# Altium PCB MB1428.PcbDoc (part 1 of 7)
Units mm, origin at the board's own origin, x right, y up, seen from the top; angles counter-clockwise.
Board outline 55.88 x 152.4 mm, 4 copper layers (Top Layer, Signal Layer 1, Signal Layer 2, Bottom Layer), stack 1.614 mm thick; 396 components, 227 nets, 1346 pads, 1469 vias.
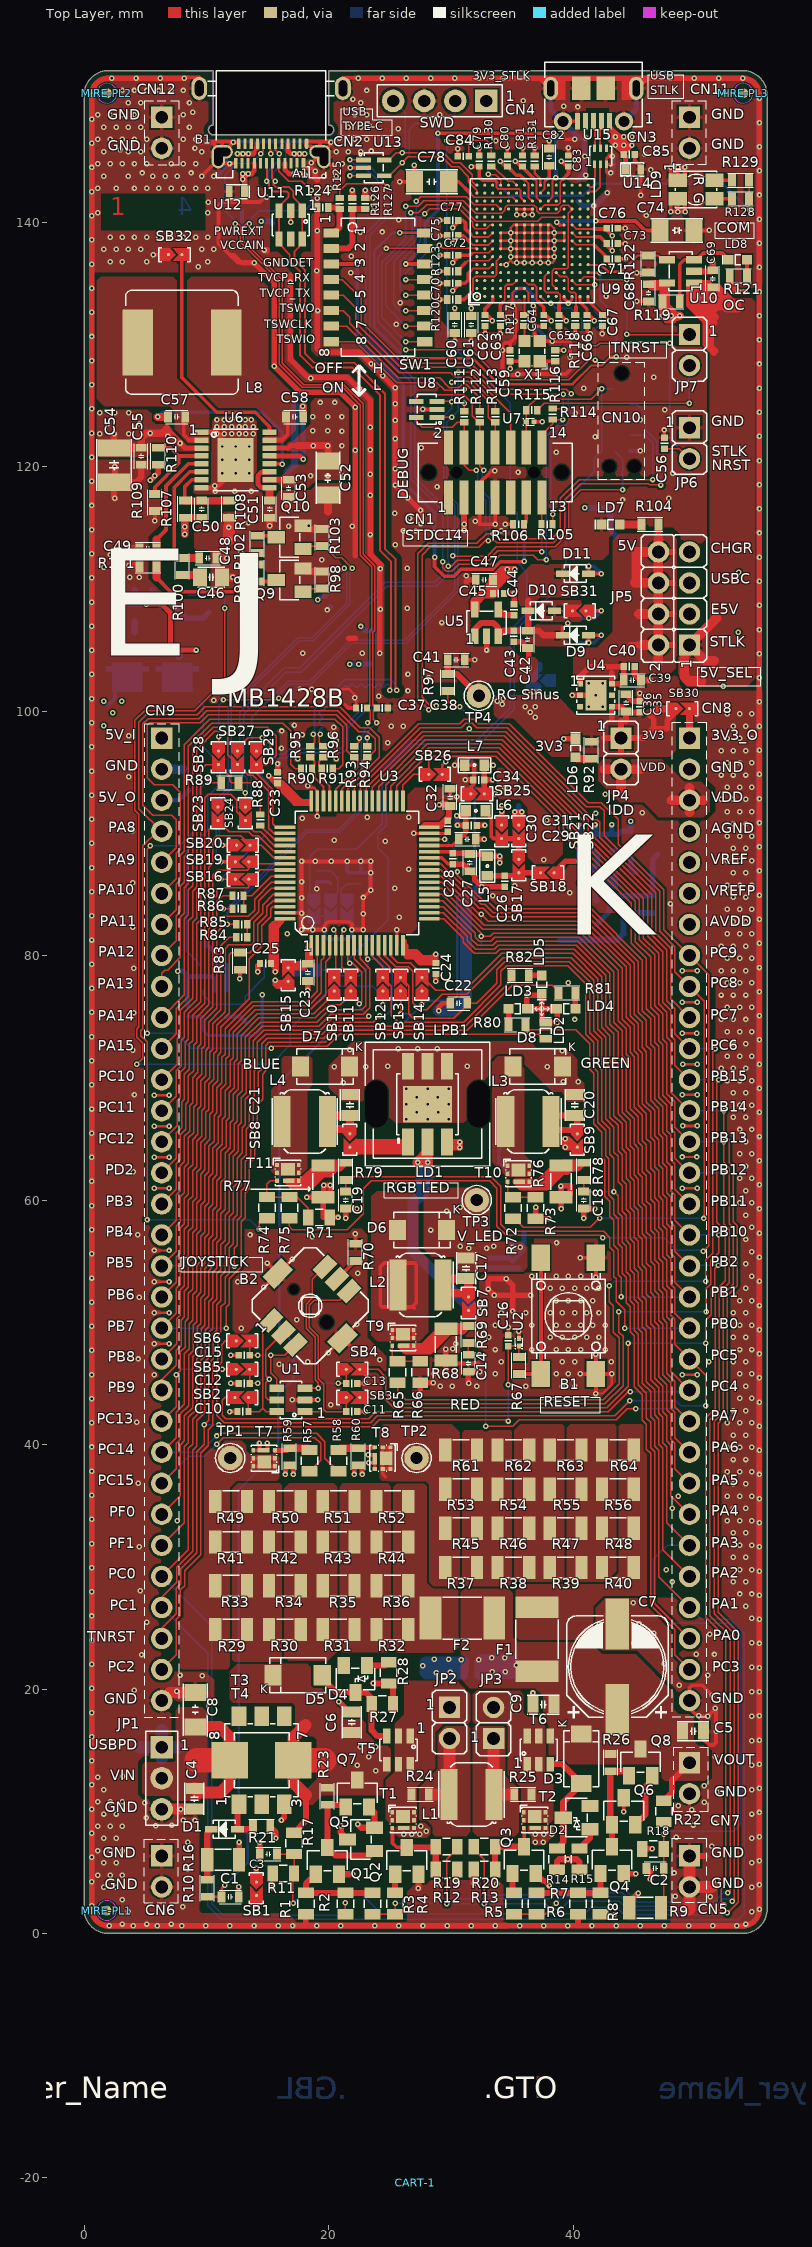
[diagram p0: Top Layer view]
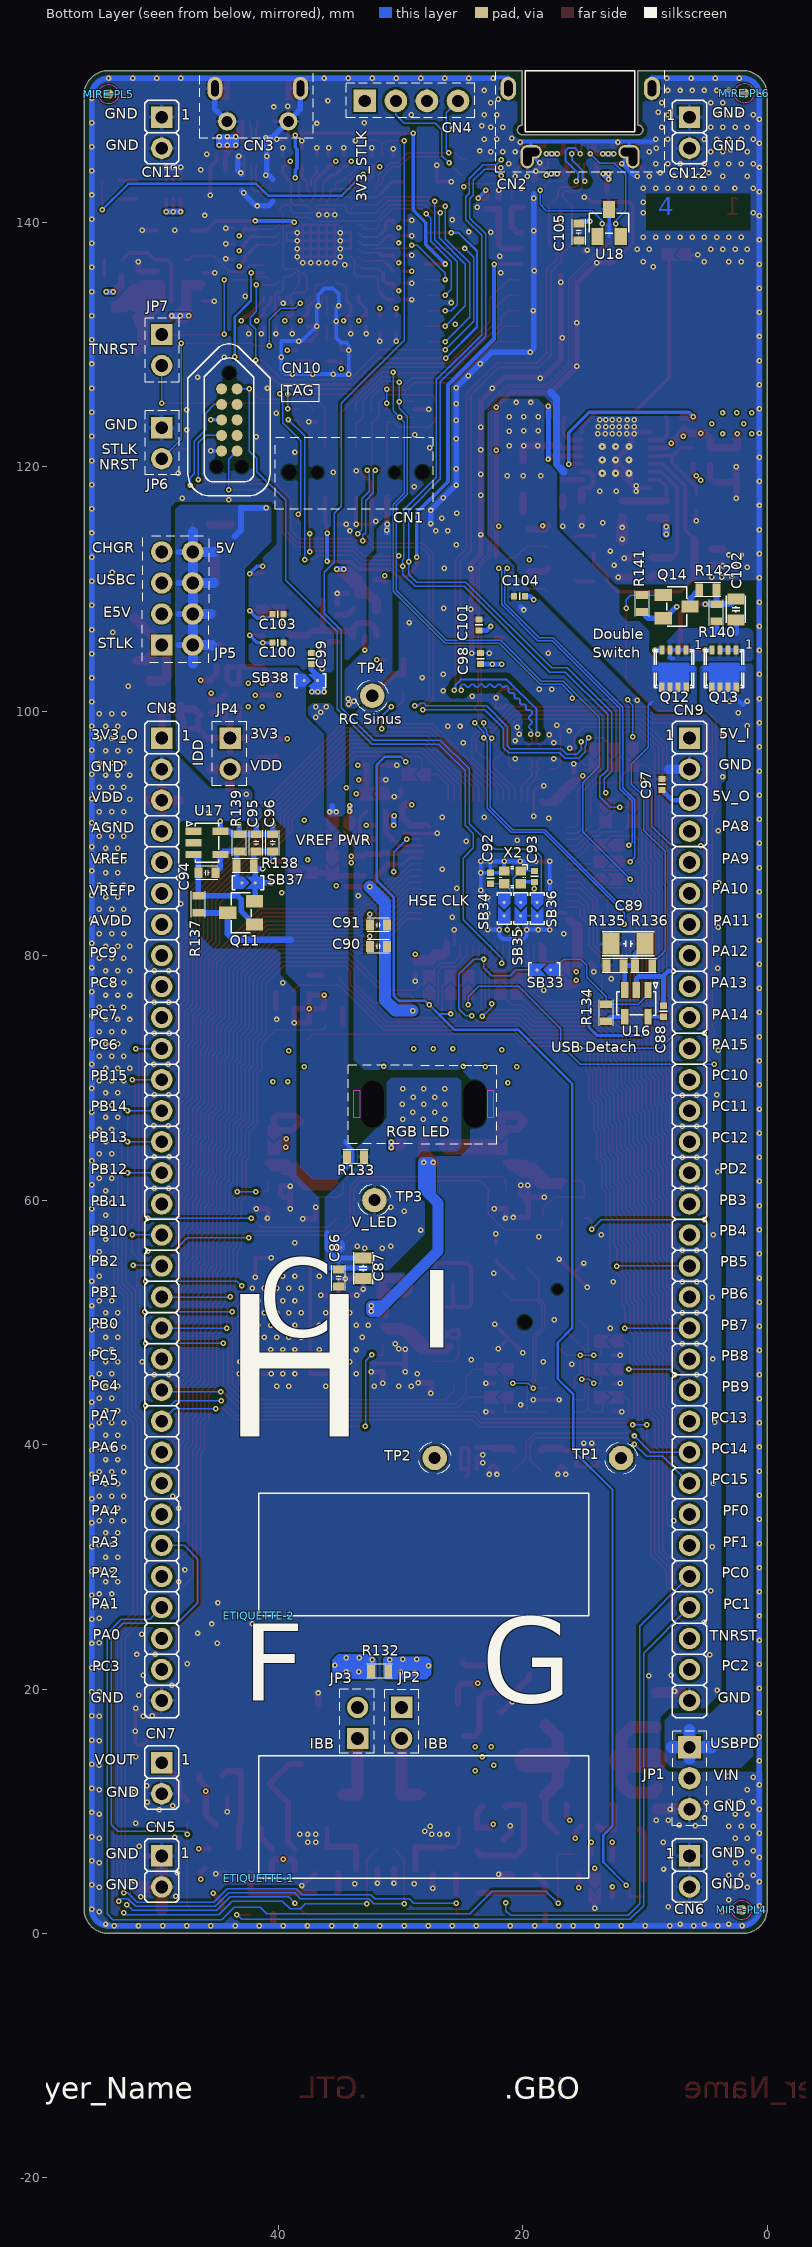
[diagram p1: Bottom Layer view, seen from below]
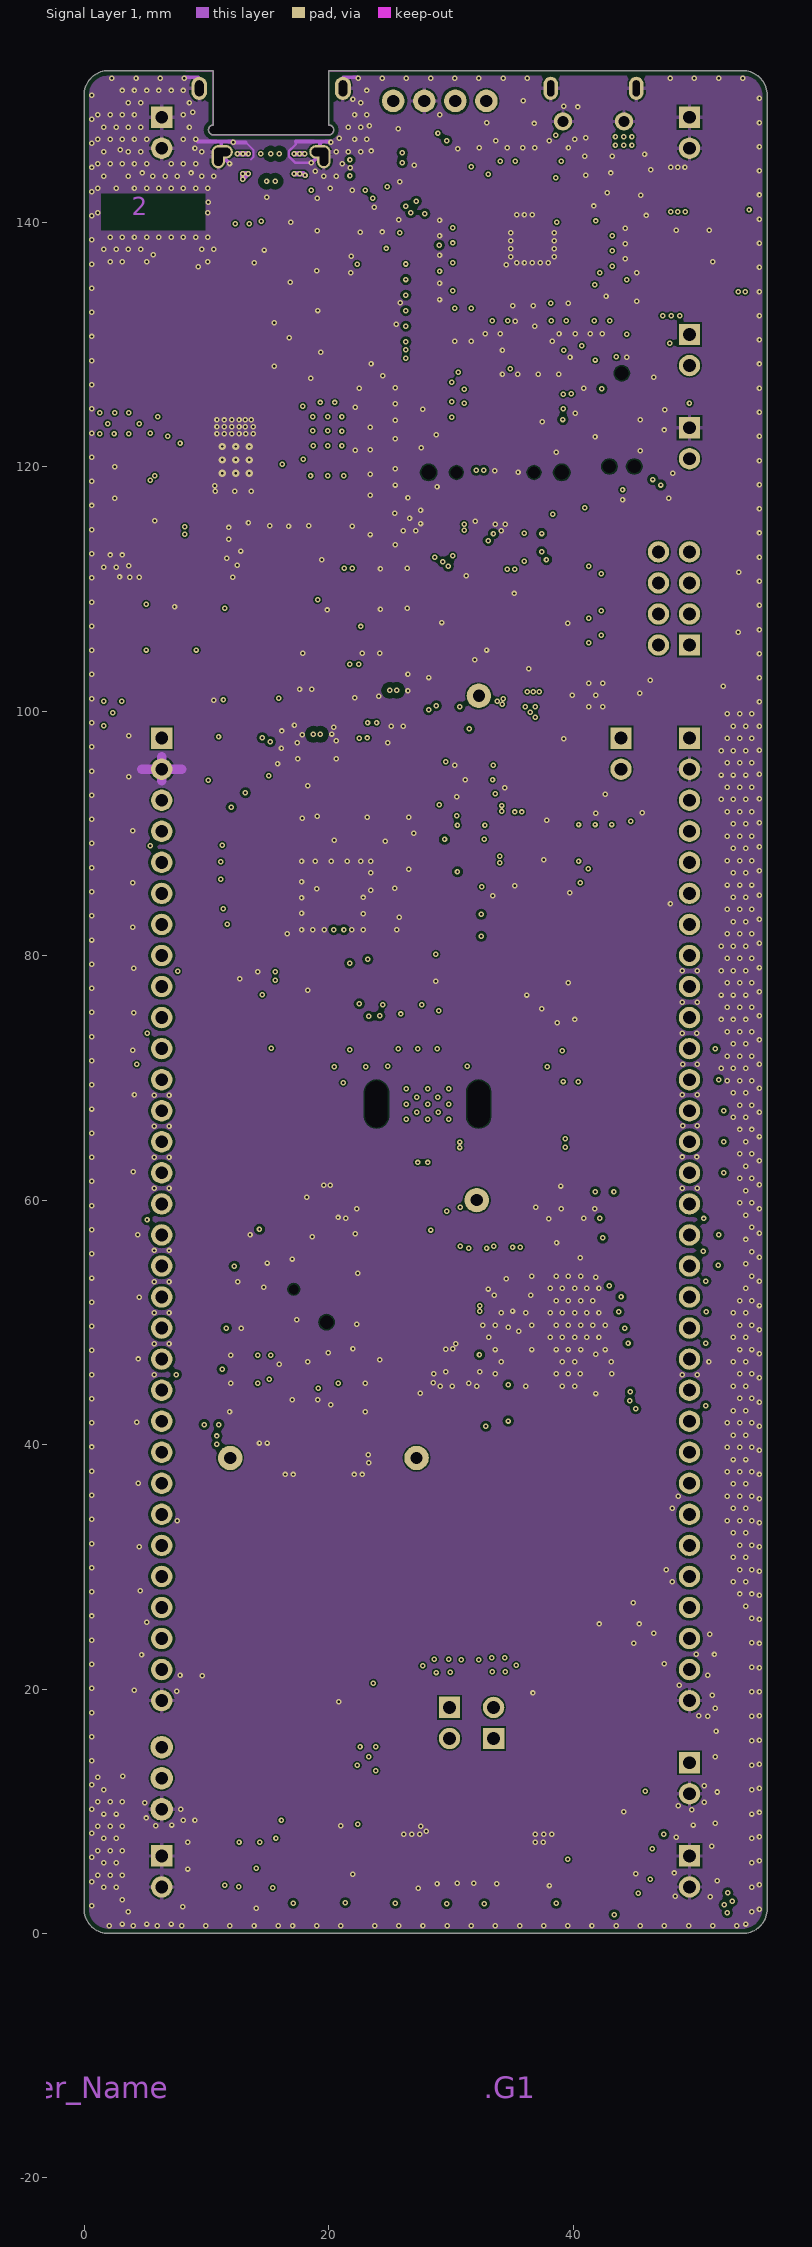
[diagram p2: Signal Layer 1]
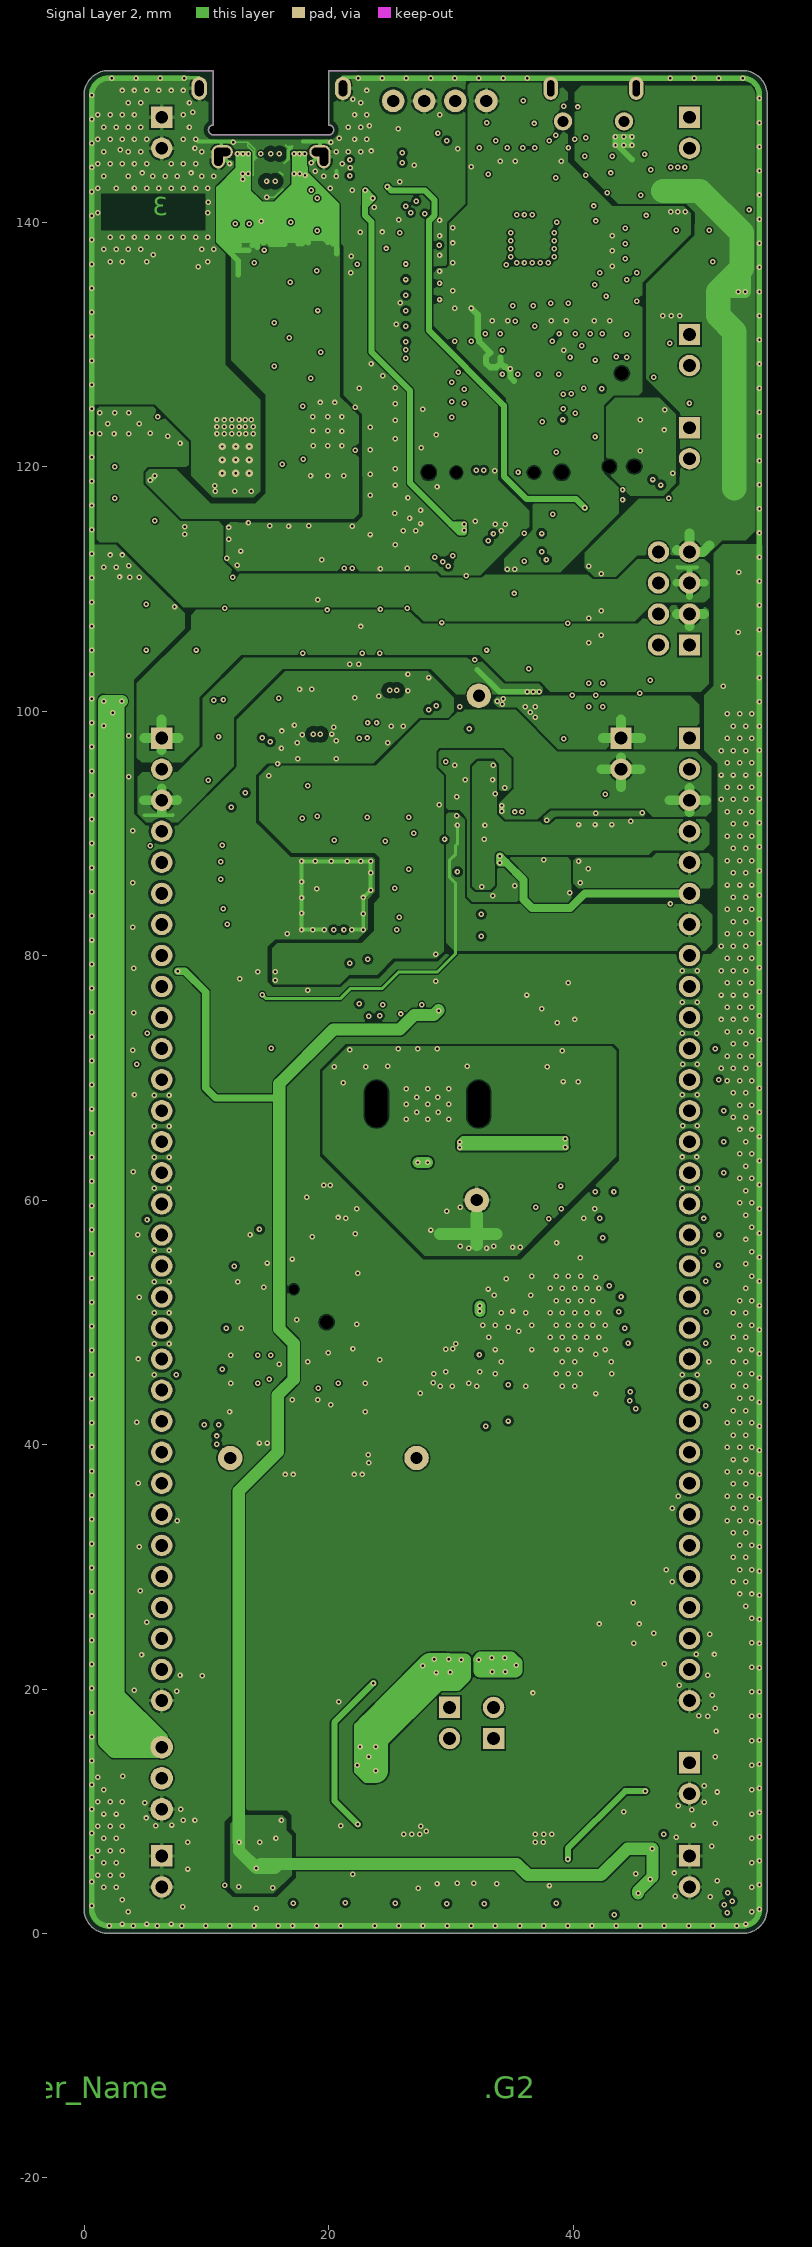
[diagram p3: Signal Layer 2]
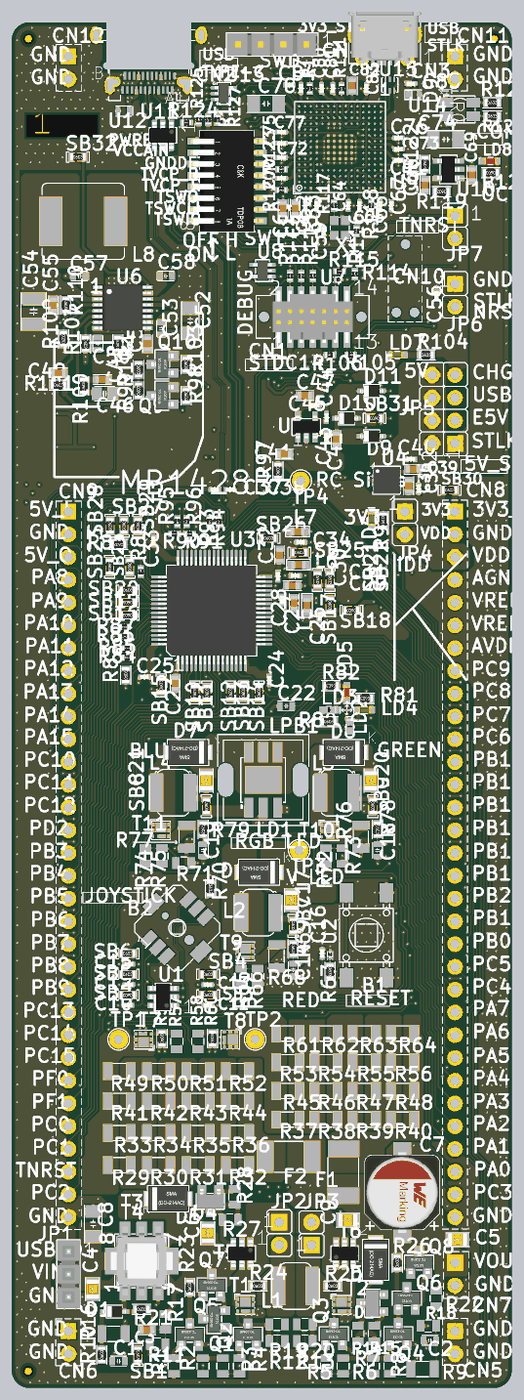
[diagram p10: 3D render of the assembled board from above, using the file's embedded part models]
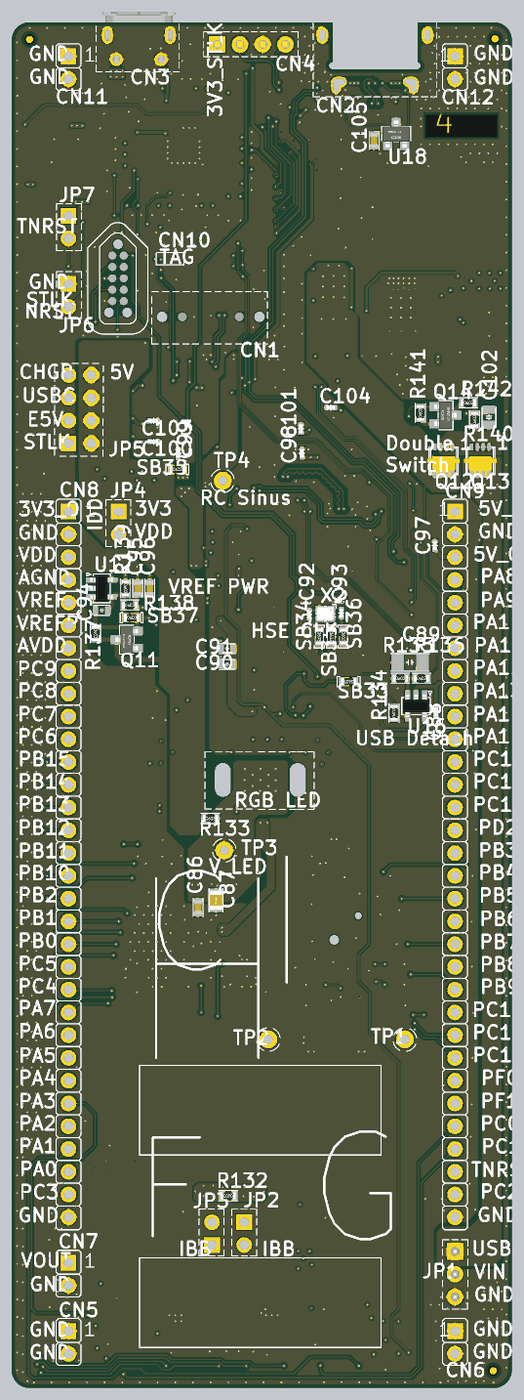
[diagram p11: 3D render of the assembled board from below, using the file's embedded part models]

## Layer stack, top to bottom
Top Solder: solder mask 0.015, Solder Resist, Dk 3.5
Top Layer: signal copper 0.042
Dielectric 1: prepreg 0.106, PP-IT-180A, Dk 4.2
Signal Layer 1: signal copper 0.035
Dielectric 2: core 1.248, FR4, Dk 4.2
Signal Layer 2: signal copper 0.035
Dielectric 3: prepreg 0.106, PP-IT-180A, Dk 4.2
Bottom Layer: signal copper 0.042
Bottom Solder: solder mask 0.015, Solder Resist, Dk 3.5

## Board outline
0,2 ccw(c2,2) 2,0 53.88,0 ccw(c53.88,2) 55.88,2 55.88,150.4 ccw(c53.88,150.4) 53.88,152.4 20.025,152.4 20.025,147.95 cw(c20.025,147.55) 20.425,147.55 cw(c20.025,147.55) 20.025,147.15 10.575,147.15 cw(c10.575,147.55) 10.175,147.55 cw(c10.575,147.55) 10.575,147.95 10.575,152.4 2,152.4 ccw(c2,150.4) 0,150.4

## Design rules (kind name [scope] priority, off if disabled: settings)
BoardOutlineClearance [All] p1: gap=0.4 ignorepadtopadclearanceinfootprint=FALSE
Clearance Clearance_BGA-STLINK_U2 [WithinRoom('RoomDefinition_U2') And TouchesRoom('RoomDefinition_U2')] p1: gap=0.12 ignorepadtopadclearanceinfootprint=TRUE except(0.2: Arc-THPad Arc-Fill Arc-Hole Track-THPad Track-Fill Track-Hole SMDPad-SMDPad SMDPad-THPad SMDPad-Fill SMDPad-Hole THPad-THPad THPad-Fill THPad-Hole Via-Fill Via-Hole Fill-Fill Fill-Hole Poly-Poly Poly-Hole Region-Hole Text-Hole)
Clearance Clearance_USB [InNetClass('USB')] p2: gap=0.226 ignorepadtopadclearanceinfootprint=TRUE except(0.12: Arc-Via Arc-Text Track-Via Track-Text SMDPad-Via SMDPad-Text THPad-Via THPad-Text Via-Via Via-Text Fill-Text Poly-Text Region-Text Text-Text; 0.452: Arc-Poly Track-Poly SMDPad-Poly THPad-Poly Via-Poly Fill-Poly Poly-Poly)
Clearance Clearance_SIG-55OHM [InNetClass('SIG-55OHM')] p3: gap=0.212 ignorepadtopadclearanceinfootprint=TRUE except(0.12: Arc-Via Arc-Region Arc-Text Track-Via Track-Region Track-Text SMDPad-Via SMDPad-Region SMDPad-Text THPad-Via THPad-Region THPad-Text Via-Via Via-Region Via-Text Fill-Region Fill-Text Poly-Region Poly-Text Region-Region Region-Text Text-Text)
Clearance [All] p4: gap=0.12 ignorepadtopadclearanceinfootprint=TRUE except(0.2: Arc-THPad Arc-Fill Track-THPad Track-Fill SMDPad-SMDPad SMDPad-THPad SMDPad-Fill THPad-THPad THPad-Fill Via-Fill Fill-Fill Poly-Poly)
ComponentClearance [All] p1 off: gap=0.025 collisioncheckmode=3 verticalgap=0.025 showdistances=TRUE
DiffPairsRouting DiffPairsRouting_USB [InDifferentialPairClass('DIFF_USB')] p1: maxlimit=0.226 minlimit=0.226 mostfreqgap=0.226 toplayer_minwidth=0.16 toplayer_maxwidth=0.16 toplayer_prefwidth=0.16 midlayer1_minwidth=0.16 midlayer1_maxwidth=0.16 midlayer1_prefwidth=0.16 midlayer2_minwidth=0.16 midlayer2_maxwidth=0.16 midlayer2_prefwidth=0.16 bottomlayer_minwidth=0.16 bottomlayer_maxwidth=0.16 bottomlayer_prefwidth=0.16 maxuncoupledlength=50
FanoutControl Fanout_BGA [IsBGA] p1: bgadir=Out bgaviamode=Closest fanoutstyle=Auto fanoutdirection=Alternating viagrid=0.025 // Fanout_BGA (Default Rule)
FanoutControl Fanout_LCC [IsLCC] p2: bgadir=Out bgaviamode=Closest fanoutstyle=Auto fanoutdirection=Alternating viagrid=0.025 // Fanout_LCC (Default Rule)
FanoutControl Fanout_SOIC [IsSOIC] p3: bgadir=Out bgaviamode=Closest fanoutstyle=Auto fanoutdirection=Alternating viagrid=0.025 // Fanout_SOIC (Default Rule)
FanoutControl Fanout_Small [(CompPinCount < 5)] p4: bgadir=Out bgaviamode=Closest fanoutstyle=Auto fanoutdirection=OutThenIn viagrid=0.025 // Fanout_Small (Default Rule)
FanoutControl Fanout_Default [All] p5: bgadir=Out bgaviamode=Closest fanoutstyle=Auto fanoutdirection=Alternating viagrid=0.025 // Fanout_Default (Default Rule)
Height [All] p1 off: minheight=0 maxheight=100 prefheight=0.5
HoleSize [All] p1: absolutevalues=TRUE maxlimit=10 minlimit=0.15 maxpercent=80.000 minpercent=20.000
HoleToHoleClearance [All] p1: gap=0 allowstackedmicrovias=TRUE
Length Length_USB [InNetClass('USB')] p1: maxlimit=80 minlimit=1
MatchedLengths [InDifferentialPairClass('DIFF_USB')] p1: tolerance=1 checknetsindiffpair=TRUE checkdiffpairvsdiffpair=FALSE checkxsignals=FALSE checkothers=FALSE
MatchedLengths MatchedLengths_T_SW [InNetClass('T_SW')] p2: tolerance=0.5 checknetsindiffpair=FALSE checkdiffpairvsdiffpair=TRUE checkxsignals=TRUE checkothers=TRUE
MatchedLengths MatchedLengths_PA13-14 [InNetClass('PA13-14')] p3: tolerance=0.5 checknetsindiffpair=FALSE checkdiffpairvsdiffpair=TRUE checkxsignals=TRUE checkothers=TRUE
MinimumSolderMaskSliver [All] p1: minsoldermaskwidth=0
PlaneClearance [All] p1: clearance=0.6
PolygonConnect PolygonConnect_33 [All vs IsNamedPolygon('NETD6_1_L01_P164')] p1: connectstyle=Direct reliefconductorwidth=0.254 reliefentries=4 polygonreliefangle="90 Angle" airgapwidth=0.254
PolygonConnect PolygonConnect_32 [All vs IsNamedPolygon('V_LED_L01_P160')] p2: connectstyle=Direct reliefconductorwidth=0.254 reliefentries=4 polygonreliefangle="90 Angle" airgapwidth=0.254
PolygonConnect PolygonConnect_31 [All vs IsNamedPolygon('NETD8_1_L01_P154')] p3: connectstyle=Direct reliefconductorwidth=0.254 reliefentries=4 polygonreliefangle="90 Angle" airgapwidth=0.254
PolygonConnect PolygonConnect_30 [All vs IsNamedPolygon('V_LED_L01_P156')] p4: connectstyle=Direct reliefconductorwidth=0.254 reliefentries=4 polygonreliefangle="90 Angle" airgapwidth=0.254
PolygonConnect PolygonConnect_29 [All vs IsNamedPolygon('NETD7_1_L01_P158')] p5: connectstyle=Direct reliefconductorwidth=0.254 reliefentries=4 polygonreliefangle="90 Angle" airgapwidth=0.254
PolygonConnect PolygonConnect_28 [All vs IsNamedPolygon('V_IN_L01_P342')] p6: connectstyle=Direct reliefconductorwidth=0.254 reliefentries=4 polygonreliefangle="90 Angle" airgapwidth=0.254
PolygonConnect PolygonConnect_27 [All vs IsNamedPolygon('NETJP3_1_L01_P340')] p7: connectstyle=Direct reliefconductorwidth=0.254 reliefentries=4 polygonreliefangle="90 Angle" airgapwidth=0.254
PolygonConnect PolygonConnect_26 [All vs IsNamedPolygon('NETJP2_2_L01_P338')] p8: connectstyle=Direct reliefconductorwidth=0.254 reliefentries=4 polygonreliefangle="90 Angle" airgapwidth=0.254
PolygonConnect PolygonConnect_25 [All vs IsNamedPolygon('GND_L01_P336')] p9: connectstyle=Direct reliefconductorwidth=0.254 reliefentries=4 polygonreliefangle="90 Angle" airgapwidth=0.254
PolygonConnect PolygonConnect_24 [All vs IsNamedPolygon('NETF1_1_L01_P320') Or  IsNamedPolygon('NETR38_2_L01_P322') Or  IsNamedPolygon('VOUT_L01_P292') Or  IsNamedPolygon('NETR29_1_L01_P306') Or  IsNamedPolygon('NETR31_2_L01_P314') Or  IsNamedPolygon('NETF2_1_L01_P318') Or  IsNamedPolygon('NETR37_1_L01_P316') Or  IsNamedPolygon('NETR29_2_L01_P308') Or  IsNamedPolygon('NETR30_2_L01_P312') Or  IsNamedPolygon('NETR39_2_L01_P326') Or  IsNamedPolygon('NETR37_2_L01_P324')] p10: connectstyle=Direct reliefconductorwidth=0.254 reliefentries=4 polygonreliefangle="90 Angle" airgapwidth=0.254
PolygonConnect PolygonConnect_23 [All vs IsNamedPolygon('NETJP3_2_L01_P294')] p11: connectstyle=Direct reliefconductorwidth=0.254 reliefentries=4 polygonreliefangle="90 Angle" airgapwidth=0.254
PolygonConnect PolygonConnect_22 [All vs IsNamedPolygon('NETJP2_1_L01_P296')] p12: connectstyle=Direct reliefconductorwidth=0.254 reliefentries=4 polygonreliefangle="90 Angle" airgapwidth=0.254
PolygonConnect PolygonConnect_21 [All vs IsNamedPolygon('GND_L01_P334')] p13: connectstyle=Direct reliefconductorwidth=0.254 reliefentries=4 polygonreliefangle="90 Angle" airgapwidth=0.254
PolygonConnect PolygonConnect_20 [All vs IsNamedPolygon('GND_L01_P332')] p14: connectstyle=Direct reliefconductorwidth=0.254 reliefentries=4 polygonreliefangle="90 Angle" airgapwidth=0.254
PolygonConnect PolygonConnect_18 [All vs IsNamedPolygon('VIN_L01_P304')] p15: connectstyle=Direct reliefconductorwidth=0.254 reliefentries=4 polygonreliefangle="90 Angle" airgapwidth=0.254
PolygonConnect PolygonConnect_17 [All vs IsNamedPolygon('VOUT_L01_P292')] p16: thpad.connectstyle=Relief thpad.reliefconductorwidth=0.3 thpad.reliefentries=4 thpad.polygonreliefangle="90 Angle" thpad.airgapwidth=0.15 smdpad.connectstyle=Relief smdpad.reliefconductorwidth=0.3 smdpad.reliefentries=4 smdpad.polygonreliefangle="90 Angle" smdpad.airgapwidth=0.15 via.connectstyle=Direct via.reliefconductorwidth=0.254 via.reliefentries=4 via.polygonreliefangle="90 Angle" via.airgapwidth=0.254
PolygonConnect PolygonConnect_16 [All vs IsNamedPolygon('VOUT_L01_P292')] p17: thpad.connectstyle=Relief thpad.reliefconductorwidth=0.3 thpad.reliefentries=4 thpad.polygonreliefangle="90 Angle" thpad.airgapwidth=0.15 smdpad.connectstyle=Relief smdpad.reliefconductorwidth=0.3 smdpad.reliefentries=4 smdpad.polygonreliefangle="90 Angle" smdpad.airgapwidth=0.15 via.connectstyle=Direct via.reliefconductorwidth=0.254 via.reliefentries=4 via.polygonreliefangle="90 Angle" via.airgapwidth=15
PolygonConnect PolygonConnect_15 [All vs IsNamedPolygon('VOUT_L01_P292')] p18: thpad.connectstyle=Relief thpad.reliefconductorwidth=0.3 thpad.reliefentries=4 thpad.polygonreliefangle="90 Angle" thpad.airgapwidth=0.2 smdpad.connectstyle=Relief smdpad.reliefconductorwidth=0.3 smdpad.reliefentries=4 smdpad.polygonreliefangle="90 Angle" smdpad.airgapwidth=0.2 via.connectstyle=Direct via.reliefconductorwidth=0.254 via.reliefentries=4 via.polygonreliefangle="90 Angle" via.airgapwidth=0.254
PolygonConnect PolygonConnect_14 [All vs IsNamedPolygon('VOUT_L01_P292')] p19: connectstyle=Direct reliefconductorwidth=0.254 reliefentries=4 polygonreliefangle="90 Angle" airgapwidth=0.254
PolygonConnect PolygonConnect_6 [All vs IsNamedPolygon('USBPD_VBUS_L01_P024')] p20: connectstyle=Direct reliefconductorwidth=0.254 reliefentries=4 polygonreliefangle="90 Angle" airgapwidth=0.254
PolygonConnect PolygonConnect_5 [All vs IsNamedPolygon('GND_L01_P022')] p21: connectstyle=Direct reliefconductorwidth=0.254 reliefentries=4 polygonreliefangle="90 Angle" airgapwidth=0.254
PolygonConnect PolygonConnect_4 [All vs IsNamedPolygon('PROG_L01_P020')] p22: connectstyle=Direct reliefconductorwidth=0.254 reliefentries=4 polygonreliefangle="90 Angle" airgapwidth=0.254
PolygonConnect PolygonConnect_3 [All vs IsNamedPolygon('GND_L01_P018')] p23: connectstyle=Direct reliefconductorwidth=0.254 reliefentries=4 polygonreliefangle="90 Angle" airgapwidth=0.254
PolygonConnect PolygonConnect_2 [All vs IsNamedPolygon('5V_USBPD_L01_P016')] p24: connectstyle=Direct reliefconductorwidth=0.254 reliefentries=4 polygonreliefangle="90 Angle" airgapwidth=0.254
PolygonConnect PolygonConnect_1 [All vs IsNamedPolygon('SW2_L01_P014')] p25: connectstyle=Direct reliefconductorwidth=0.254 reliefentries=4 polygonreliefangle="90 Angle" airgapwidth=0.254
PolygonConnect [All vs IsNamedPolygon('SW1_L01_P012')] p26: connectstyle=Direct reliefconductorwidth=0.254 reliefentries=4 polygonreliefangle="90 Angle" airgapwidth=0.254
PolygonConnect PolygonConnect__DEFAULT [All] p27: thpad.connectstyle=Relief thpad.reliefconductorwidth=0.3 thpad.reliefentries=4 thpad.polygonreliefangle="90 Angle" thpad.airgapwidth=0.15 smdpad.connectstyle=Relief smdpad.reliefconductorwidth=0.3 smdpad.reliefentries=4 smdpad.polygonreliefangle="90 Angle" smdpad.airgapwidth=0.15 via.connectstyle=Direct via.reliefconductorwidth=0.254 via.reliefentries=4 via.polygonreliefangle="45 Angle" via.airgapwidth=0.254
RoomDefinition RoomDefinition_U2 [InComponentClass('Room Definition 1')] p1: confinementstyle=ConfineIn formatcopy=TRUE lockcomponents=FALSE outline 31.096,132.891 31.096,144.059 42.264,144.059 42.264,132.891
RoutingLayers RoutingLayers_SIG-55OHM [InNetClass('SIG-55OHM')] p1: top layer_v5=TRUE mid layer 1_v5=FALSE mid layer 2_v5=FALSE bottom layer_v5=TRUE
RoutingLayers RoutingLayers_USB [InNetClass('USB')] p2: top layer_v5=TRUE mid layer 1_v5=FALSE mid layer 2_v5=FALSE bottom layer_v5=TRUE
RoutingLayers [All] p3: top layer_v5=TRUE mid layer 1_v5=TRUE mid layer 2_v5=TRUE bottom layer_v5=TRUE
RoutingVias RoutingVias_GND-EP [InNet('GND')] p1: holewidth=0.3 width=0.6 viastyle="Through Hole" minholewidth=0.2 minwidth=0.45 maxholewidth=0.3 maxwidth=0.6
RoutingVias [All] p2: holewidth=0.2 width=0.45 viastyle="Through Hole" minholewidth=0.2 minwidth=0.45 maxholewidth=0.2 maxwidth=0.45
ShortCircuit ShortCircuit_T3-T4_2 [InPadClass('PC_T3-T4_2')] p1: allowed=TRUE
ShortCircuit ShortCircuit_T3-T4_4 [InPadClass('PC_T3-T4_4')] p2: allowed=TRUE
ShortCircuit ShortCircuit_T3-T4_5 [InPadClass('PC_T3-T4_5')] p3: allowed=TRUE
ShortCircuit ShortCircuit_T3-T4_6 [InPadClass('PC_T3-T4_6')] p4: allowed=TRUE
ShortCircuit [All] p5: allowed=FALSE
SilkToSilkClearance [All] p1: silktosilkclearance=0
SilkToSolderMaskClearance [IsPad] p1: minsilkscreentomaskgap=0 clearancetoexposedcopper=TRUE
SolderMaskExpansion [All] p1: expansion=0.05
UnpouredPolygon [All] p1: allowunpoured=TRUE allowshelved=TRUE
Width Width_ALIMS [InNetClass('ALIMS')] p1: maxlimit=10 minlimit=0.12 preferedwidth=0.3
Width Width_GND [InNetClass('GND')] p2: maxlimit=10 minlimit=0.12 preferedwidth=0.3 minimp=50.000000 maximp=50.000000 favimp=50.000000
Width Width_SIG-55OHM [InNetClass('SIG-55OHM')] p3: maxlimit=0.12 minlimit=0.12 preferedwidth=0.12 minimp=50.000000 maximp=50.000000 favimp=50.000000
Width [All] p4: maxlimit=10 minlimit=0.12 preferedwidth=0.12
13 further rules are at their usual default settings.

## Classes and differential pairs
pad class PC_T3-T4_6: T3-6 T4-6
pad class PC_T3-T4_5: T3-5 T4-5
pad class PC_T3-T4_4: T3-4 T4-4
pad class PC_T3-T4_2: T3-2 T4-2
component class "Room Definition 1": U12
net class PA13-14: PA13 PA14
net class T_SW: T_SWCLK T_SWDIO
net class SWAPABLE: PA0 PA1 PA2 PA3 PA4 PA5 PA6 PA7 PA8 PA9 PA10 PA11 PA12 PA13 PA14 PA15 PB0 PB1 PB2 PB3 PB4 PB5 PB6 PB7 PB8 PB9 PB10 PB11 PB12 PB13 PB14 PB15 PC0 PC1 PC2 PC3 PC4 PC5 PC6 PC7 PC8 PC9 PC10 PC11 PC12 PC13 PC14 PC15 PD2 PF0 PF1
net class SIG-55OHM: MCO NetR84_1 NetR86_1 NetR88_2 NetSB10_2 NetSB11_2 PA0 PA1 PA2 PA3 PA4 PA5 PA6 PA7 PA8 PA9 PA10 PA11 PA12 PA13 PA14 PA15 PB0 PB1 PB2 PB3 PB4 PB5 PB6 PB7 PB8 PB9 PB10 PB11 PB12 PB13 PB14 PB15 PC0 PC1 PC2 PC3 PC4 PC5 PC6 PC7 PC8 PC9 PC10 PC11 PC12 PC13 PC14 PC15 PD2 PF0 PF1 STLK_MCO STLK_SWCLK STLK_SWDIO STLK_VCP_RX STLK_VCP_TX T_NRST T_SWCLK T_SWCLKa T_SWDIO T_SWDIOa T_SWOa T_VCP_RX T_VCP_TX
differential pair class DIFF_USB: D USB_DEV_HS USB_DEV_HS_CN USBPDFS_D
net class ALIMS: 1S 3V3 3V3_OUT 3V3_STLK 5V 5V_OUT 5V_USB_CHGR 5V_USB_STLK 5V_USBPD 5V_USBPD_1A_PROTECT 5V_VIN NetC42_2 NetC44_2 NetD2_3 USB_PD_VBUS USBPD_550mA_PROTECT USBPD_VBUS V_IN V_LED VBAT VC VDD VIN VOUT VREF VREFP
net class GND: AGND AVDD GND GNDDet GNDDetect
net class USB: D_N D_P USB_DEV_HS_CN_N USB_DEV_HS_CN_P USB_DEV_HS_N USB_DEV_HS_P USBPDFS_D_N USBPDFS_D_P
differential pair USB_DEV_HS: +USB_DEV_HS_P -USB_DEV_HS_N
differential pair USB_DEV_HS_CN: +USB_DEV_HS_CN_P -USB_DEV_HS_CN_N
differential pair D: +D_P -D_N
differential pair USBPDFS_D: +USBPDFS_D_P -USBPDFS_D_N

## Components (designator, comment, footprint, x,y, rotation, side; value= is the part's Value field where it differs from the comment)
B1 "" SWI_WEALTHMETAL_TD-0341_4P_BLACK 39.625,50.525 r0 top value=SWITCH
B2 "" SWI_XIEJIA_MT-008A_6P 18.5,51.35 r45 top value=MT-008A
C1 "" C0603_H0P8 11.95,3 r180 top value=680pF
C2 "" C0603_H0P8 46.725,5.325 r0 top value="6.8nF, 50V"
C3 "" C0603 15.075,6.5 r0 top value="22nF, 50V"
C4 "" C0805_H0P85 9.025,11.025 r90 top value="100nF, 50V"
C5 "" C0805_H0P85 49.825,16.55 r180 top value="100nF, 50V"
C6 "" C0805_H0P85 21.9,17.275 r270 top value="100nF, 50V"
C7 "" CPOL_WURTH_WCAP-ASLL_8X10P5 43.625,21.825 r270 top value="100µF, 35V"
C8 "Capacitor" C1206_H1P6 9.1,18.3 r270 top value="47uF, 25V"
C9 "" C0805_H0P85 37.575,18.725 r0 top value="100nF, 50V"
C10 "" C0402 13,42.7 r0 top value=100nF
C11 "" C0402 21.9,42.7 r180 top value=100nF
C12 "" C0402 13.1,45 r0 top value=100nF
C13 "" C0402 21.9,45 r180 top value=100nF
C14 "Capacitor" C0603_H0P8 31.45,46.65 r90 top value="470pF, 100V"
C15 "" C0402 13.1,47.3 r0 top value=100nF
C16 "" C0402 34.7,48.5 r270 top value=100nF
C17 "" C0805_H0P85 31.25,54.425 r90 top value=1uF
C18 "Capacitor" C0603_H0P8 40.87,60 r90 top value="470pF, 100V"
C19 "Capacitor" C0603_H0P8 21.4,60 r90 top value="470pF, 100V"
C20 "" C0805_H0P85 40.145,67.775 r90 top value=1uF
C21 "" C0805_H0P85 21.75,67.775 r90 top value=1uF
C22 "Capacitor" C0603_H0P8 30.65,76.1 r0 top value="470pF, 100V"
C23 "" C0603 18.289,78.629 r90 top value=1uF
C24 "" C0402 28.789,78.954 r90 top value=100nF
C25 "" C0402 14.85,79.35 r0 top value=100nF
C26 "" C0402 34.414,86.079 r90 top value=100nF
C27 "" C0603 31.564,87.604 r90 top value=10uF
C28 "" C0402 30.164,87.929 r270 top value=100nF
C29 "" C0603 31.35,89.525 r180 top value=1uF
C30 "" C0402 29.75,90.575 r90 top value=100nF
C31 "" C0402 31.675,90.65 r180 top value=100nF
C32 "" C0603 29.95,92.95 r270 top value=4.7uF
C33 "" C0402 15.825,94.55 r270 top value=100nF
C34 "" C0402 32.289,94.379 r0 top value=100nF
C35 "" C0402 45.475,100.35 r270 top value=100nF
C36 "" C0603 44.35,100.675 r270 top value=1uF
C37 "" C0402 22.7,100.25 r0 top value=390pF
C38 "" C0402 24.4,100.25 r180 top value=390pF
C39 "" C0603 44.85,102.525 r180 top value=1uF
C40 "" C0402 44.6,103.65 r180 top value=100nF
C41 "" C0603 30.45,104.2 r180 top value=10nF
C42 "" C0603 36.275,105.875 r90 top value=1uF
C43 "" C0402 35.15,106.125 r90 top value=100nF
C44 "" C0402 35.175,108.3 r270 top value=10nF
C45 "" C0402 33.9,109.625 r180 top value=100nF
C46 "Capacitor" C0805_KEMET_IPC-7351_DENSITY-LEVEL-B_H1P10 10.4,110.95 r180 top value=27nF
C47 "" C0603 32.75,110.75 r0 top value=1uF
C48 "" C0603 10.125,112.525 r180 top value=10pF
C49 "" C0603 5.225,113.275 r0 top value=10nF
C50 "Capacitor" C0603_H0P8 9.625,116.525 r270 top value=2.7nF
C51 "" C0603 15.175,116.525 r270 top value=4.7uF
C52 "" C1206_H1P6 19.95,119.075 r90 top value="6.8uF, 50V"
C53 "Capacitor" C0603_H0P8 16.725,118.225 r90 top value="1uF, 50V"
C54 "" C1210 2.45,120.125 r90 top value=22uF
C55 "" C0603 4.675,120.85 r90 top value=1uF
C56 "" C0402 47.475,121.925 r270 top value=100nF
C57 "" C0603_H0P8 7.575,124.075 r0 top value="68nF, 50V"
C58 "" C0603_H0P8 17.225,124.075 r180 top value="68nF, 50V"
C59 "" C0402 34.855,129.075 r270 top value=100nF
C60 "" C0603 30.33,131.625 r90 top value=4.7uF
C61 "" C0603 31.68,131.625 r90 top value=1uF
C62 "" C0402 32.805,131.95 r90 top value=100nF
C63 "" C0402 34.055,131.95 r90 top value=100nF
C64 "" C0402 37.605,131.95 r90 top value=100nF
C65 "" C0402 38.855,131.95 r90 top value=100nF
C66 "" C0402 41.155,131.95 r90 top value=100nF
C67 "" C0402 42.405,131.95 r90 top value=100nF
C68 "" C0603 46.18,134.225 r90 top value=1uF
C69 "" C0603 51.43,135.375 r270 top value=1uF
C70 "" C0402 30.155,135 r0 top value=100nF
C71 "" C0402 43.205,137 r180 top value=100nF
C72 "" C0402 30.155,137.3 r0 top value=100nF
C73 "" C0402 43.205,138.25 r180 top value=100nF
C74 "" C1206_H1P15 48.505,139.325 r180 top value=2.2uF
C75 "" C0402 30.155,138.9 r0 top value=100nF
C76 "" C0402 43.205,139.5 r180 top value=100nF
C77 "" C0402 30.155,140.15 r0 top value=100nF
C78 "" C1206_H1P15 28.43,143.3 r0 top value=2.2uF
C79 "" C0402 32.33,145 r270 top value=100nF
C80 "" C0402 34.63,145 r270 top value=100nF
C81 "" C0402 35.88,145 r270 top value=100nF
C82 "" C0603 38.055,145.325 r270 top value=2.2uF
C83 "" C0402 39.63,145 r270 top value=100nF
C84 "" C0402 31.03,145.4 r0 top value=20pF
C85 "" C0402 44.6,145.55 r180 top value=100pF
C86 "" C0603 35.05,53.625 r90 bottom value=4.7uF
C87 "" C0805_H0P85 33.05,54.425 r90 bottom value="100nF, 50V"
C88 "" C0402 8.475,75.45 r270 bottom value=100nF
C89 "" C1206_H0P85 11.375,80.975 r180 bottom value=22nF
C90 "Capacitor" C0603_H0P8 31.8,80.75 r0 bottom value="470pF, 100V"
C91 "Capacitor" C0603_H0P8 31.8,82.5 r0 bottom value="470pF, 100V"
C92 "" C0402 22.639,86.329 r270 bottom value=6.8pF
C93 "" C0402 19.039,86.479 r90 bottom value=6.8pF
C94 "" C0603_H0P8 45.825,86.775 r180 bottom locked value="100pF, 50V"
C95 "" C0603 41.8,89.225 r270 bottom value=100nF
C96 "" C0603 40.45,89.225 r270 bottom value=10uF
C97 "" C0402 8.6,94 r270 bottom value=100nF
C98 "" C0402 23.45,104.3 r270 bottom value=100nF
C99 "" C0402 37.275,104.3 r270 bottom value=100nF
C100 "" C0402 40.025,105.6 r0 bottom value=100nF
C101 "" C0402 23.575,107.05 r270 bottom value=100nF
C102 "" C0805_H0P6 2.55,108.325 r270 bottom value="1nF, 50V"
C103 "" C0402 40.025,107.925 r0 bottom value=100nF
C104 "" C0402 20.25,109.4 r180 bottom value=100nF
C105 "Capacitor" C0603 15.4,139.2 r90 bottom value="100nF, 50V"
CART-1 "Comment" Sheetbox_4L2S -18,-25.75 r0 top
CN1 "" CON_STDC14_Receiver_MEDIUM 33.635,119.525 r0 top value=STDC14
CN2 "" CON_USB-TYPEC_LITKCONN-TECHNOLOGY_CNG008S130R 15.3,152.4 r180 top locked value=CNG008S130R
CN3 "" CON_USBMICROB_MOLEX_105017-0001_H2P90 41.675,152.4 r180 top locked value=USB_uB_105017-0001
CN4 "" CON_SAMTEC_TSW-104-07-G-S 29.1,149.925 r180 top value="Header 4x1"
CN5 "Header 2x1" CON_LYCONN_313102S141346 49.53,5.08 r270 bottom
CN6 "Header 2x1" CON_LYCONN_313102S141346 6.35,5.08 r270 bottom
CN7 "Header 2x1" CON_LYCONN_313102S141346 49.53,12.7 r270 bottom
CN8 "Header 32x1" CON_LYCONN_313132S141346 49.53,58.42 r270 bottom locked value=313132S141346
CN9 "Header 32x1" CON_LYCONN_313132S141346 6.35,58.42 r270 bottom locked value=313132S141346
CN10 "" CON_TAG-C_TC2050-IDC-NL 43.995,123.825 r270 bottom value=TC2050-IDC-NL
CN11 "Header 2x1" CON_LYCONN_313102S141346 49.53,147.32 r270 bottom
CN12 "Header 2x1" CON_LYCONN_313102S141346 6.35,147.32 r270 bottom
D1 "DIODE_1K_2A" DIO_SOD323_1K_2A 11.475,8.525 r180 top value=BAS70JFILM
D2 "" DIO_SOT23_SC59_1A_2NC_3K_H1P4 40.3,9.475 r90 top value=BAT54FILM
D3 "" DIO_SMA_1A_2K 40.675,14.3 r270 top value=SMAJ15A
D4 "" DIO_SOT23_SC59_1A_2NC_3K_H1P4 22.2,20.825 r180 top value=BAT54FILM
D5 "" DIO_SMA_1A_2K 17.475,21.125 r0 top value=SMAJ15A
D6 "" DIO_SMA_1A_2K 27.65,57.55 r180 top value=STPS1L40AY
D7 "" DIO_SMA_1A_2K 19.71,70.925 r180 top value=STPS1L40AY
D8 "" DIO_SMA_1A_2K 37.11,70.925 r180 top value=STPS1L40AY
D9 "" DIO_SOD323 40.2,106.205 r180 top value=BAT60JFILM
D10 "" DIO_SOD323 37.405,108.205 r180 top value=BAT60JFILM
D11 "" DIO_SOD323 40.2,111.255 r180 top value=BAT60JFILM
ETIQUETTE-1 "Comment" LOGO_ETIQUETTE 41.6,4.525 r180 bottom
ETIQUETTE-2 "Comment" LOGO_ETIQUETTE 41.6,26 r180 bottom
F1 "" PTC_EATON_FUSE_PTS1812_H0P9 37.05,24.075 r270 top value="PTC FUSE 0.2A"
F2 "" PTC_EATON_FUSE_PTS1812_H0P9 30.95,25.8 r0 top value="PTC FUSE 0.2A"
JP1 "Jumper_Header 3x1 Fitted 1-2" CON_SAMTEC_TSW-103-07-F-S 6.35,12.7 r270 top value="Shunt Fitted 1-2"
JP2 "Jumper_Header 2x1" CON_988-JIUBABA_313102S111116 29.9,17.225 r270 top value="Shunt not fitted"
JP3 "Jumper_Header 2x1" CON_988-JIUBABA_313102S111116 33.5,17.225 r90 top value="Shunt not fitted"
JP4 "Jumper_Header 2x1 Fitted" CON_988-JIUBABA_313102S111116 43.93,96.52 r270 top locked value="Shunt Fitted"
JP5 "Jumper_Header 4x2 Fitted 1-2" CON_988-JIUBABA_313208S141116 48.26,109.22 r90 top value="Shunt Fitted 1-2"
JP6 "Jumper_Header 2x1" CON_988-JIUBABA_313102S111116 49.53,121.92 r270 top value="Shunt not fitted"
JP7 "Jumper_Header 2x1 Fitted" CON_988-JIUBABA_313102S111116 49.53,129.54 r270 top value="Shunt Fitted"
L1 "Inductor" IND_SUNLORD_SWPA5040S 31.7,11.375 r270 top value="51 uH"
L2 "Inductor" IND_SUNLORD_SWPA5040S 27.525,53.05 r90 top value="100 uH"
L3 "Inductor" IND_SUNLORD_SWPA5040S 36.345,66.425 r90 top value="100 uH"
L4 "Inductor" IND_SUNLORD_SWPA5040S 18.05,66.425 r90 top value="100 uH"
L5 "BEAD" L0603 32.989,87.329 r90 top value=FCM1608KF-301T05
L6 "BEAD" L0603 32.05,91.85 r180 top value=FCM1608KF-301T05
L7 "" L0603 31.939,95.579 r0 top value=600R@100MHz
L8 "" IND_8040_WURTH_74437358068 8,130.175 r180 top value="6.8µH 4.5A"
LD1 "" LED_PLCC6-EPAD_LUMEX_SML-LX5050SIUPGUBC 28.1,67.85 r270 top value="RGB LED"
LD2 "" LED_0603_SMD-B_BLUE_H0P4 37.775,73.85 r90 top value=BLUE
LD3 "" LED_0603_ORANGE_H0P4 35.475,75.65 r0 top value=ORANGE
LD4 "" LED_0603_GREEN 39.45,75.65 r180 top value=GREEN
LD5 "" LED_0603_RED 37.45,77.625 r270 top value=RED
LD6 "" LED_0603_GREEN 40.2,96.975 r90 top value=GREEN
LD7 "" LED_0603_GREEN 43.075,115.275 r180 top value=GREEN
LD8 "" LED_0603_RED 53.48,136.925 r180 top value=RED
LD9 "" LED_BI-GR_HSMF-A201-A00J1 50.075,142.675 r270 top value=LD_BICOLOR_CMS
LPB1 "LPB-S01110101S" LIGHT_10MM-SQUARE-LIGHT-BAR_LUMEX_LPB-S01110101S 28.1,67.85 r180 top
MIRE-PL1 "Comment" MIRE_PLACE_SMD_0P8MM 1.85,1.875 r0 top
MIRE-PL2 "Comment" MIRE_PLACE_SMD_0P8MM 1.875,150.55 r0 top
MIRE-PL3 "Comment" MIRE_PLACE_SMD_0P8MM 53.925,150.55 r0 top
MIRE-PL4 "Comment" MIRE_PLACE_SMD_0P8MM 2.075,1.925 r180 bottom
MIRE-PL5 "Comment" MIRE_PLACE_SMD_0P8MM 53.875,150.475 r180 bottom
MIRE-PL6 "Comment" MIRE_PLACE_SMD_0P8MM 1.875,150.55 r180 bottom
Q1 "" ICC_SOT23-3L_H1P12 19.9,5.95 r0 top value=NDS7002A
Q2 "" ICC_SOT23-3L_H1P12 26.4,5.95 r0 top value=NDS7002A
Q3 "" ICC_SOT23-3L_H1P12 36,6 r0 top value=NDS7002A
Q4 "" ICC_SOT23-3L_H1P12 43.2,6 r0 top value=NDS7002A
Q5 "" ICC_SOT23-3L_H1P12 22.65,7.7 r90 top value=BC807
Q6 "" ICC_SOT23-3L_H1P12 44.15,10 r0 top value=BC807
Q7 "" NPN_SOT23 22.35,11.45 r0 top value=BC817
Q8 "" NPN_SOT23 45.525,14 r0 top value=BC817
Q9 "" MOS_SOT23 16.825,110.725 r90 top value=BSN20
Q10 "" MOS_SOT23 16.825,114.225 r90 top value=BSN20
Q11 "9013-SOT23" NPN_SOT23 43.025,83.5 r90 bottom value=MMBT2222ALT1G
Q12 "" MOS_POWERFLAT_3P3X3P3_P065 7.625,103.475 r0 bottom value=STL9P3LLH6
Q13 "" MOS_POWERFLAT_3P3X3P3_P065 3.525,103.475 r0 bottom value=STL9P3LLH6
Q14 "" MOS_SOT23 7.4,108.55 r270 bottom value=BSN20
R1 "" R0805 18.15,2.45 r90 top value=10K
R2 "" R0805_H0P5 21.375,2.45 r90 top value=10R
R3 "" R0805_H0P5 23.6,2.45 r90 top value=270R
R4 "" R0805_H0P5 25.45,2.45 r90 top value=270R
R5 "" R0805_H0P5 35.175,2.45 r270 top value=270R
R6 "" R0805_H0P5 37.025,2.45 r270 top value=270R
R7 "" R0805 40.4,2.45 r90 top value=10K
R8 "" R0805_H0P5 42.25,2.45 r270 top value=10R
R9 "" R1206_H0P55 45.9,2.1 r0 top value=1R
R10 "Resistor" R0603 10.075,3.7 r90 top value=0R
R11 "" R0805 16.3,4.9 r0 top value="6K8, 0.1%"
R12 "" R0805 29.65,5.25 r180 top value=10K
R13 "" R0805 32.75,5.25 r0 top value=10K
R14 "" R0805_H0P5 38.675,6.075 r270 top value=47R
R15 "" R0805_H0P5 40.525,6.075 r270 top value=10R
R16 "Resistor" R1206_H0P55 11.375,6.025 r0 top value=187R
R17 "" R0805 17.175,7.375 r90 top value="27K, 0.1%"
R18 "" R0805 46.55,6.925 r0 top value="3.3K, 0.1%"
R19 "" R0805_H0P5 29.65,7.1 r180 top value=10R
R20 "" R0805_H0P5 32.75,7.1 r180 top value=10R
R21 "Resistor" R0603 14.525,8.775 r0 top value=5K1
R22 "" R0805 47.425,10 r90 top value="13.3K, 0.1%"
R23 "" R0603 19.9,11.225 r90 top value=1K
R24 "" R0603 27.5,11.375 r0 top value=0R_0603_ULO
R25 "" R0603 35.9,11.375 r0 top value=0R_0603_ULO
R26 "" R0603 43.075,13.975 r90 top value=1K
R27 "" R0805_H0P5 24.4,18.775 r180 top value=47R
R28 "" R0805_H0P5 24.925,21.325 r90 top value=10R
R29 "" R1206_H0P55 12.025,24.875 r0 top value=33R
R30 "" R1206_H0P55 16.425,24.875 r0 top value=33R
R31 "" R1206_H0P55 20.825,24.875 r0 top value=33R
R32 "" R1206_H0P55 25.225,24.875 r0 top value=33R
R33 "" R1206_H0P55 12.025,28.45 r0 top value=33R
R34 "" R1206_H0P55 16.425,28.45 r0 top value=33R
R35 "" R1206_H0P55 20.825,28.45 r0 top value=33R
R36 "" R1206_H0P55 25.225,28.45 r0 top value=33R
R37 "" R1206_H0P55 30.85,29.95 r0 top value=33R
R38 "" R1206_H0P55 35.125,29.95 r0 top value=33R
R39 "" R1206_H0P55 39.4,29.95 r0 top value=33R
R40 "" R1206_H0P55 43.675,29.95 r0 top value=33R
R41 "" R1206_H0P55 12.025,32.025 r0 top value=33R
R42 "" R1206_H0P55 16.425,32.025 r0 top value=33R
R43 "" R1206_H0P55 20.825,32.025 r0 top value=33R
R44 "" R1206_H0P55 25.225,32.025 r0 top value=33R
R45 "" R1206_H0P55 30.85,33.15 r0 top value=33R
R46 "" R1206_H0P55 35.125,33.15 r0 top value=33R
R47 "" R1206_H0P55 39.4,33.15 r0 top value=33R
R48 "" R1206_H0P55 43.675,33.15 r0 top value=33R
R49 "" R1206_H0P55 12.025,35.35 r0 top value=33R
R50 "" R1206_H0P55 16.425,35.35 r0 top value=33R
R51 "" R1206_H0P55 20.825,35.35 r0 top value=33R
R52 "" R1206_H0P55 25.225,35.35 r0 top value=33R
R53 "" R1206_H0P55 30.85,36.35 r0 top value=33R
R54 "" R1206_H0P55 35.125,36.35 r0 top value=33R
R55 "" R1206_H0P55 39.4,36.35 r0 top value=33R
R56 "" R1206_H0P55 43.675,36.35 r0 top value=33R
R57 "" R0805_H0P5 18.45,38.675 r90 top value=10R
R58 "" R0805_H0P5 20.8,38.675 r90 top value=10R
R59 "" R0603 16.8,39 r90 top value=10K
R60 "" R0603 22.425,39 r90 top value=10K
R61 "" R1206_H0P55 30.85,39.55 r0 top value=33R
R62 "" R1206_H0P55 35.125,39.55 r0 top value=33R
R63 "" R1206_H0P55 39.4,39.55 r0 top value=33R
R64 "" R1206_H0P55 43.675,39.55 r0 top value=33R
R65 "" R0805_H0P5 25.65,45.925 r90 top value=10R
R66 "" R0805 27.5,45.925 r90 top value=10K
R67 "" R0603 35.575,46.475 r270 top value=100R
R68 "" R1206_H0P55 29.6,48.175 r90 top value=3R01
R69 "" R0603 31.45,49 r270 top value=33R
R70 "" R0603 22.2,55.725 r270 top value=100R
R71 "" R0805 19.225,58.575 r180 top value=10K
R72 "" R0805_H0P5 35.095,59.35 r90 top value=10R
R73 "" R0805 36.945,59.35 r90 top value=10K
R74 "" R0805_H0P5 14.95,59.375 r90 top value=10R
R75 "" R0805_H0P5 16.8,59.375 r90 top value=10R
R76 "" R1206_H0P55 39.02,61.525 r90 top value=3R01
R77 "" R1206_H0P55 19.55,61.525 r90 top value=3R01
R78 "" R0603 40.87,62.35 r270 top value=33R
R79 "" R0603 21.4,62.35 r270 top value=33R
R80 "" R0603 35.425,74.35 r0 top value=1K
R81 "" R0603 39.5,76.95 r180 top value=330R
R82 "" R0603 35.675,78.375 r180 top value=1K
R83 "" R0603 12.75,79.55 r90 top value=10K
R84 "" R0402 12.9,81.5 r180 top value=0R
R85 "" R0402 12.9,82.55 r180 top value=0R
R86 "" R0402 12.6,83.85 r180 top value=0R
R87 "" R0402 12.6,84.9 r180 top value=0R
R88 "" R0402 14.425,91.1 r270 top value=47R
R89 "" R0603 11.925,94.125 r180 top value=470R
R90 "" R0402 18.189,95.304 r0 top value=0R
R91 "" R0402 19.889,95.304 r180 top value=0R
R92 "" R0603 41.5,96.8 r90 top value=330R
R93 "" R0402 22.1,96.675 r270 top value=0R
R94 "" R0402 23.164,96.675 r270 top value=0R
R95 "" R0402 18.514,96.679 r270 top value=0R
R96 "" R0402 19.564,96.679 r270 top value=0R
R97 "" R0603 29.75,102.35 r90 top value=15K
R98 "" R0603 19.475,110.725 r270 top value=10K
R99 "Resistor" R0603 14.175,111.3 r90 top value=180K
R100 "" R0603_H0P45 8.025,111.825 r90 top value=4K22
R101 "Resistor" R0603_H0P45 5.225,111.9 r0 top value=64.9K
R102 "Resistor" R0603_H0P45 14.175,113.65 r270 top value=59K
R103 "" R0603 19.475,114.2 r270 top value=10K
R104 "" R0603 46.3,115.275 r0 top value=820R
R105 "" R0402 37.875,115.282 r180 top value=47R
R106 "" R0402 35.55,115.285 r0 top value=100R
R107 "Resistor" R0603 8.25,116.525 r270 top value=200K
R108 "Resistor" R0603 11.85,116.525 r90 top value=49K9
R109 "" R0603_H0P45 5.8,117.075 r90 top value=787K
R110 "" R0603_H0P45 6.05,120.85 r270 top value=1M05
R111 "" R0402 31.1,124.082 r270 top value=47R
R112 "" R0402 32.375,124.082 r270 top value=47R
R113 "" R0402 33.65,124.082 r270 top value=47R
R114 "" R0402 38.33,124.3 r270 top value=47R
R115 "" R0402 36.625,124.632 r180 top value=47R
R116 "" R0402 38.53,129.075 r270 top value=10K
R117 "" R0402 36.03,131.95 r90 top value=100R
R118 "" R0402 40.18,131.95 r90 top value=10K
R119 "" R0603 48.03,133.5 r180 top value=100K
R120 "" R0402 30.155,133.675 r0 top value=10K
R121 "" R0603 53.53,135.625 r180 top value=1K
R122 "" R0603 46.155,136.575 r270 top value=10K
R123 "" R0402 30.155,135.975 r0 top value=10K
R124 "" R0402 19.525,141.2 r0 top value=4K7
R125 "" R0402 20.905,141.525 r270 top value=2K7
R126 "" R0402 21.955,141.525 r90 top value=4K7
R127 "" R0402 23.005,141.525 r90 top value=4K7
R128 "" R0603 53.7,141.925 r0 top value=330R
R129 "" R0603 53.7,143.425 r0 top value=330R
R130 "" R0402 33.305,145 r90 top value=100R
R131 "" R0402 36.855,145 r270 top value=3K
R132 "" R0603 31.7,21.45 r0 bottom value=0R_0603_ULO
R133 "" R0603 33.675,63.55 r180 bottom value=0R_0603_ULO
R134 "" R0603 13.175,75.325 r90 bottom value=43K
R135 "" R0603 12.45,79.175 r180 bottom value=49K9
R136 "" R0603 10.1,79.175 r180 bottom value=330K
R137 "" R0603 46.525,84.2 r270 bottom value=180R
R138 "" R0603 42.7,87.35 r180 bottom locked value="10K, 0.1%"
R139 "" R0603 43.175,89.225 r270 bottom value="33K, 0.1%"
R140 "" R0603 4.15,108.05 r90 bottom value=56K
R141 "" R0603 10.225,108.8 r90 bottom value=10K
R142 "" R0603 4.85,109.925 r180 bottom value=330R
SB1 "" SOLDER-BRIDGE_R0603-0R 14.1,3.7 r270 top
SB2 "" SOLDER-BRIDGE_R0603-0R 12.95,43.85 r180 top
SB3 "" SOLDER-BRIDGE_R0603-0R 21.95,43.85 r0 top
SB4 "" SOLDER-BRIDGE_R0603-0R 21.95,46.15 r0 top
SB5 "" SOLDER-BRIDGE_R0603-0R 12.95,46.15 r0 top
SB6 "" SOLDER-BRIDGE_R0603-0R 12.95,48.475 r0 top
SB7 "" SOLDER-BRIDGE_R0603-0R 31.45,51.575 r270 top
SB8 "" SOLDER-BRIDGE_R0603-0R 21.75,64.925 r270 top
SB9 "" SOLDER-BRIDGE_R0603-0R 40.35,64.925 r270 top
SB10 "" SOLDER-BRIDGE_R0603-0R 20.464,77.604 r90 top
SB11 "" SOLDER-BRIDGE_R0603-0R 21.814,77.604 r90 top
SB12 "" SOLDER-BRIDGE_R0603-0R 24.439,77.604 r90 top
SB13 "" SOLDER-BRIDGE_R0603-0R 25.889,77.604 r90 top
SB14 "" SOLDER-BRIDGE_R0603-0R 27.639,77.604 r90 top
SB15 "" SOLDER-BRIDGE_R0603-0R 16.7,78.4 r90 top
SB16 "" SOLDER-BRIDGE_R0603-0R 12.975,86.25 r180 top
SB17 "" SOLDER-BRIDGE_R0603-0R 35.564,87.379 r270 top
SB18 "" SOLDER-BRIDGE_R0603-0R 37.95,86.775 r180 top
SB19 "" SOLDER-BRIDGE_R0603-0R 12.975,87.675 r180 top
SB20 "" SOLDER-BRIDGE_R0603-0R 12.975,89.025 r0 top
SB21 "" SOLDER-BRIDGE_R0603-0R 34.164,90.179 r270 top
SB22 "" SOLDER-BRIDGE_R0603-0R 35.564,90.179 r270 top
SB23 "" SOLDER-BRIDGE_R0603-0R 10.95,91.65 r270 top
SB24 "" SOLDER-BRIDGE_R0603-0R 13.2,91.65 r270 top
SB25 "" SOLDER-BRIDGE_R0603-0R 32.139,93.229 r0 top
SB26 "" SOLDER-BRIDGE_R0603-0R 28.7,94.825 r0 top
SB27 "" SOLDER-BRIDGE_R0603-0R 12.55,96.225 r270 top
SB28 "" SOLDER-BRIDGE_R0603-0R 11,96.225 r270 top
SB29 "" SOLDER-BRIDGE_R0603-0R 14.1,96.225 r270 top
SB30 "" SOLDER-BRIDGE_R0603-0R 48.925,100.2 r0 top
SB31 "SB_ON" SOLDER-BRIDGE_R0603-0R 40.555,108.205 r180 top
SB32 "" SOLDER-BRIDGE_R0603-0R 7.4,137.35 r0 top
SB33 "" SOLDER-BRIDGE_R0603-0R 18.225,78.825 r0 bottom
SB34 "" SOLDER-BRIDGE_R0603-0R 21.514,83.854 r270 bottom
SB35 "" SOLDER-BRIDGE_R0603-0R 20.164,83.854 r270 bottom
SB36 "" SOLDER-BRIDGE_R0603-0R 18.814,83.854 r270 bottom
SB37 "" SOLDER-BRIDGE_R0603-0R 42.475,85.95 r180 bottom
SB38 "" SOLDER-BRIDGE_R0603-0R 37.375,102.5 r180 bottom
SW1 "TDP08H1SBD1_180" SWI_C&K_TDP08H1SBD1 24.05,134.675 r270 top value=TDP08H1SBD1_Symbol_180
T1 "" MOS_POWERFLAT_2X2_P065 26.113,9.275 r270 top value=STL6N2VH5
T2 "" MOS_POWERFLAT_2X2_P065 36.875,9.275 r270 top value=STL6N2VH5
T3 "" TRS_WURTH_750317809 14.525,14.175 r90 top value=750317809
T4 "" TRS_WURTH_749251125 14.525,14.175 r90 top value=749251125
T5 "" MOS_SOT23-6L 25.725,15 r180 top value=STT4P3LLH6
T6 "" MOS_SOT23-6L 37.2,15 r0 top value=STT4P3LLH6
T7 "" MOS_POWERFLAT_2X2_P065 14.725,38.875 r90 top value=STL6N2VH5
T8 "" MOS_POWERFLAT_2X2_P065 24.425,38.875 r180 top value=STL6N2VH5
T9 "" MOS_POWERFLAT_2X2_P065 26.1,48.725 r270 top value=STL6N2VH5
T10 "" MOS_POWERFLAT_2X2_P065 35.545,62.15 r270 top value=STL6N2VH5
T11 "" MOS_POWERFLAT_2X2_P065 16.688,62.225 r270 top value=STL6N2VH5
TP1 "" TP_PTH_1MM_2MM 11.95,38.9 r180 top value=TP
TP2 "" TP_PTH_1MM_2MM 27.2,38.9 r90 top value=TP
TP3 "" TP_PTH_1MM_2MM 32.125,60 r90 top value=TP
TP4 "" TP_PTH_1MM_2MM 32.3,101.25 r90 top value=TP
U1 "" ESD_SOT23-6L 16.925,43.65 r90 top value=ESDA6V1-5SC6
U2 "" ESD_ST0201 35.575,48.375 r90 top value=ESDALC6V1-1U2
U3 "STM32G474RET6U" ICC_LQFP64_10X10_P050 22.339,86.754 r0 top
U4 "" ICC_DFN6-EPAD_3X3_P095 41.875,101.3 r270 top value=LD39050PU33R
U5 "" REG_SOT23-5L 32.925,107.225 r0 top value=LD3985M33R
U6 "" ICC_TSOP65P640X110_HS-17N 12.4,120.55 r0 top value=LTC3114HFE-1
U7 "" ESD_ST0201 36.485,123.675 r0 top value=ESDALC6V1-1U2
U8 "" ESD_SOT323-5L 28.025,124.682 r90 top value=ESDALC6V1W5
U9 "" ICC_UFBGA201_176+25_10X10_P065 36.68,138.475 r90 top value=ST-LINKV3E_SWD
U10 "" MOS_SOT23-5L 48.805,135.975 r90 top value=STMPS2151STR
U11 "" ESD_SOT23-6L 16.9,139.775 r180 top value=USBLC6-2SC6
U12 "" ESD_QFN1610_2N_1K_2A 12.5,142.5 r180 top value=ESDA25P35-1U1M
U13 "" ESD_SOT323-5L 23.705,144.45 r270 top value=ESDALC6V1W5
U14 "" ESD_QFN2_1P6X1_P125 44.925,144.3 r0 top value=ESDA7P60-1U1M
U15 "" ESD_QFN-6L_1P7X1P5_P050 42.25,145.4 r0 top value=ECMF02-2AMX6
U16 "" AOP_SOT23-5L_H1P45 10.7,76.1 r0 bottom value=TSV911ILT
U17 "" ICC_SOT23-5L_H1P45 45.825,89.225 r270 bottom value=TL1431ACL5T
U18 "" ESD_SOT23 12.925,139.925 r180 bottom value=ESDA6V1L
X1 "OSCILLATOR_4_PINS" OSC_NDK_NZ2520SB_4P 36.655,129.45 r90 top value="NZ2520SH 25MHz"
X2 "" CRY_NX2016SA_4P 20.839,86.404 r0 bottom value="NX2016SA 24MHz"

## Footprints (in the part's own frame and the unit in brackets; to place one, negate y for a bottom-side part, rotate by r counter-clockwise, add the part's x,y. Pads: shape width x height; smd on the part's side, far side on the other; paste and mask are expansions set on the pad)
AOP_SOT23-5L_H1P45 [mm]
  rect 0.6x1.3 smd mask+0.05: 1(-0.95,-1.1) 2(0,-1.1) 3(0.95,-1.1) 4(0.95,1.1) 5(-0.95,1.1)
  silkscreen extent -1.75,-1.68 1.6,0.97, body extent -1.52,-1.25 1.52,1.25, height 1.45
C0402 [mm]
  rect 0.51x0.56 smd mask+0.05: 1(-0.45,0) 2(0.45,0)
  silkscreen extent 0,-0.3 0,0.3, body extent -0.5,-0.3 0.5,0.3, height 0.4
C0603 [mm]
  rect 0.64x0.89 smd mask+0.05: 1(-0.7,0) 2(0.7,0)
  silkscreen extent -1.05,-0.55 1.02,0.55, body extent -0.9,-0.5 0.9,0.5, height 1.4
C0603_H0P8 [mm] "MCD-01540"
  rect 0.64x0.89 smd mask+0.05: 1(-0.7,0) 2(0.7,0)
  silkscreen extent -0.9,-0.55 0.9,0.55, body extent -0.9,-0.5 0.9,0.5, height 1
C0805_H0P6 [mm] "MCD-01549"
  rect 0.9x1.4 smd mask+0.05: 1(-0.85,0) 2(0.85,0)
  silkscreen extent -1.1,-0.77 1.1,0.77, body extent -1.1,-0.7 1.1,0.7, height 0.7
C0805_H0P85 [mm] "MCD-01525"
  rect 0.9x1.4 smd mask+0.05: 1(-0.85,0) 2(0.85,0)
  silkscreen extent -1.3,-0.77 1.3,0.77, body extent -1.1,-0.73 1.1,0.73, height 0.95
C0805_KEMET_IPC-7351_DENSITY-LEVEL-B_H1P10 [mm] "MCD-01719"
  rect 1.15x1.45 smd mask+0.05: 1(-0.9,0) 2(0.9,0)
  silkscreen extent -1.1,-0.82 1.1,0.82, body extent -1,-0.63 1,0.63, height 1.2
C1206_H0P85 [mm]
  rect 1.4x1.78 smd mask+0.05: 1(-1.4,0) 2(1.4,0)
  silkscreen extent -2.12,-0.97 2.15,0.97, body extent -1.6,-0.8 1.6,0.8, height 0.95
C1206_H1P6 [mm]
  rect 1.4x1.78 smd mask+0.05: 1(-1.4,0) 2(1.4,0)
  silkscreen extent -2.12,-0.97 2.15,0.97, body extent -1.7,-0.9 1.7,0.9, height 1.8
C1206_H1P15 [mm]
  rect 1.4x1.78 smd mask+0.05: 1(-1.4,0) 2(1.4,0)
  silkscreen extent -2.12,-0.97 2.15,0.97, body extent -1.7,-0.9 1.7,0.9, height 1.35
C1210 [mm]
  rect 1.4x2.6 smd mask+0.05: 1(-1.4,0) 2(1.4,0)
  silkscreen extent -2.1,-1.43 2.1,1.43, body extent -1.75,-1.35 1.75,1.35, height 2.5
CON_988-JIUBABA_313102S111116 [mm] "MCD-01660"
  rect 1.75x1.75 hole 1.05 mask+0.05: 1(-1.27,0)
  round 1.75 hole 1.05 mask+0.05: 2(1.27,0)
  silkscreen extent -2.67,-1.4 2.54,1.4, body extent -2.67,-1.4 2.54,1.4, height 8.94
CON_988-JIUBABA_313208S141116 [mm] "MCD-01661"
  rect 1.75x1.75 hole 1.05 mask+0.05: 1(-3.81,-1.27)
  round 1.75 hole 1.05 mask+0.05: 2(-3.81,1.27) 3(-1.27,-1.27) 4(-1.27,1.27) 5(1.27,-1.27) 6(1.27,1.27) 7(3.81,-1.27) 8(3.81,1.27)
  silkscreen extent -5.21,-2.67 5.21,2.67, body extent -5.21,-2.67 5.21,2.67, height 8.94
CON_LYCONN_313102S141346 [mm] "MCD-01668"
  rect 1.75x1.75 hole 1.05 mask+0.05: 1(-1.27,0)
  round 1.75 hole 1.05 mask+0.05: 2(1.27,0)
  silkscreen extent -2.67,-1.4 2.54,1.4, body extent -2.67,-1.4 2.54,1.4, height 8.38
CON_LYCONN_313132S141346 [mm] "MCD-01728"
  rect 1.75x1.75 hole 1.05 mask+0.05: 1(-39.37,0)
  round 1.75 hole 1.05 mask+0.05: 2(-36.83,0) 3(-34.29,0) 4(-31.75,0) 5(-29.21,0) 6(-26.67,0) 7(-24.13,0) 8(-21.59,0) 9(-19.05,0) 10(-16.51,0) 11(-13.97,0) 12(-11.43,0) 13(-8.89,0) 14(-6.35,0) 15(-3.81,0) 16(-1.27,0) 17(1.27,0) 18(3.81,0) 19(6.35,0) 20(8.89,0) 21(11.43,0) 22(13.97,0) 23(16.51,0) 24(19.05,0) 25(21.59,0) 26(24.13,0) 27(26.67,0) 28(29.21,0) 29(31.75,0) 30(34.29,0) 31(36.83,0) 32(39.37,0)
  silkscreen extent -40.77,-1.4 40.77,1.4, body extent -40.77,-1.4 40.77,1.4, height 8.38
CON_SAMTEC_TSW-103-07-F-S [mm]
  rect 1.85x1.85 / inner round 1.85 / far side rect 1.85x1.85 hole 1 mask+0.05: 1(-2.54,0)
  round 1.85 hole 1 mask+0.05: 2(0,0) 3(2.54,0)
  silkscreen extent -3.85,-1.3 3.85,1.3, body extent -3.91,-1.37 3.91,1.37, height 8.38
CON_SAMTEC_TSW-104-07-G-S [mm]
  rect 1.85x1.85 / inner round 1.85 / far side rect 1.85x1.85 hole 1 mask+0.05: 1(-3.81,0)
  round 1.85 hole 1 mask+0.05: 2(-1.27,0) 3(1.27,0) 4(3.81,0)
  silkscreen extent -5.12,-1.3 5.12,1.3, body extent -5.21,-1.37 5.18,1.37, height 8.38
CON_STDC14_Receiver_MEDIUM [mm] "compatible with FTSH-107-01-L-DV,-K,-A,-P,-ES"
  round 0 hole 1.19 unplated mask+0.05: 0(-5.445,0) 0(5.445,0)
  round 0 hole 0.97 unplated mask+0.05: 0(-3.175,0) 0(3.175,0)
  rect 0.74x2.79 smd mask+0.05: 1(-3.81,-2.032) 2(-3.81,2.032) 3(-2.54,-2.032) 4(-2.54,2.032) 5(-1.27,-2.032) 6(-1.27,2.032) 7(0,-2.032) 8(0,2.032) 9(1.27,-2.032) 10(1.27,2.032) 11(2.54,-2.032) 12(2.54,2.032) 13(3.81,-2.032) 14(3.81,2.032)
  silkscreen extent -6.3,-2.39 6.3,2.39, body extent -6.3,-2.92 6.3,2.92, height 6.6
CON_TAG-C_TC2050-IDC-NL [mm]
  round 0.9 smd paste+0 mask+0.05: 1(-2.54,-0.635) 2(-1.27,-0.635) 3(0,-0.635) 4(1.27,-0.635) 5(2.54,-0.635) 6(2.54,0.635) 7(1.27,0.635) 8(0,0.635) 9(-1.27,0.635) 10(-2.54,0.635)
  round 0 hole 1.1 unplated mask+0.05: 11(-3.81,0) 12(3.81,-1.015) 13(3.81,1.015)
  silkscreen extent -6.22,-3.4 6.22,3.33, body extent -6.28,-3.46 6.28,3.39, height 13
CON_USB-TYPEC_LITKCONN-TECHNOLOGY_CNG008S130R [mm] "MCD01679__Doc Pin 1 = B12 et Doc Pin 13 = A1. The thickness of the pcb must be 0.8mm"
  oval 1.1x1.9 hole 0.7 slot 1.5 at 90 deg mask+0.05: 1(-4.32,7.05) 4(4.32,7.05)
  oval 1.75x1.1 hole 0.7 slot 1.35 at 0 deg mask+0.05: 2(-3.995,6.65) 5(3.995,6.65)
  oval 1.3x1.9 hole 0.7 slot 1.3 at 90 deg mask+0.05: 3(-5.875,1.45) 6(5.875,1.45)
  rect 0.3x0.85 smd mask+0.05: A1(-2.645,7.58) A12(2.895,7.58) B1(2.645,5.98)
  rect 0.25x0.85 smd mask+0.05: A2(-2.125,7.58) A3(-1.625,7.58) A4(-1.125,7.58) A5(-0.625,7.58) A6(-0.125,7.58) A7(0.375,7.58) A8(0.875,7.58) A9(1.375,7.58) A10(1.875,7.58) A11(2.375,7.58) B2(2.125,5.98) B3(1.625,5.98) B4(1.125,5.98) B5(0.625,5.98) B6(0.125,5.98) B7(-0.375,5.98) B8(-0.875,5.98) B9(-1.375,5.98) B10(-1.875,5.98) B11(-2.375,5.98)
  oval 0.3x0.85 smd mask+0.05: B12(-2.895,5.98)
  Keep-Out Layer lines w0.1: 7,0 4.725,0 4.725,4.45 ccw(c4.725,4.85) 4.725,5.25 -4.725,5.25 ccw(c-4.725,4.85) -4.725,4.45 -4.725,0 -7,0
  silkscreen extent -5.18,0 5.18,8.75, body extent -5.97,0 5.97,8.75, height 2.33
CON_USBMICROB_MOLEX_105017-0001_H2P90 [mm]
  rect 0.4x1.35 smd mask+0.05: 1(-1.3,4.15) 2(-0.65,4.15) 3(0,4.15) 4(0.65,4.15) 5(1.3,4.15)
  round 1.5 hole 0.9 mask+0.05: 6(-2.5,4.15) 7(2.5,4.15)
  oval 1.2x1.9 hole 0.6 slot 1.3 at 90 deg mask+0.05: 8(3.5,1.45) 9(-3.5,1.45)
  rect 1.5x1.9 smd mask+0.05: 10(-1,1.45) 11(1,1.45)
  Top Layer region: -3.5,2.4 -2.3,2.4 -2.3,0.5 -3.5,0.5 -3.5,2.4
  Top Layer region: 2.3,2.4 3.5,2.4 3.5,0.5 2.3,0.5 2.3,2.4
  silkscreen extent -4,-0.7 4,4.6, body extent -4.1,-1.15 4.1,4.66, height 2.9
CPOL_WURTH_WCAP-ASLL_8X10P5 [mm] "MCD-01683"
  rect 4.2x1.9 smd mask+0.05: 1(3.5,0) 2(-3.5,0)
  silkscreen extent -4.15,-4.15 4.22,4.15, body extent -4.5,-4.15 4.5,4.15, height 10.5
CRY_NX2016SA_4P [mm]
  rect 0.85x0.75 smd mask+0.05: 1(-0.675,-0.525) 2(0.675,-0.525) 3(0.675,0.525) 4(-0.675,0.525)
  silkscreen extent -1.22,-1.02 1.05,0.85, body extent -1.05,-0.85 1.05,0.85, height 0.7
DIO_SMA_1A_2K [mm]
  rect 1.4x1.64 smd mask+0.05: 1(2.015,0) 2(-2.015,0)
  silkscreen extent -2.3,-1.45 2.3,1.45, body extent -2.75,-1.45 2.75,1.45, height 2.7
DIO_SOD323 [mm]
  rect 1.06x0.54 smd mask+0.05: 1(-1.07,0) 2(1.07,0)
  silkscreen extent -0.9,-0.72 0.9,0.72, body extent -1.3,-0.78 1.3,0.78, height 1.17
DIO_SOD323_1K_2A [mm] "MCD-01530"
  rect 1.06x0.54 smd mask+0.05: 1(1.07,0) 2(-1.07,0)
  silkscreen extent -0.9,-0.72 0.9,0.72, body extent -1.3,-0.78 1.3,0.78, height 1.2
DIO_SOT23_SC59_1A_2NC_3K_H1P4 [mm] "MCD-01524"
  rect 1x1.4 smd mask+0.05: 1(-0.95,-1.1) 2(0.95,-1.1) 3(0,1.1)
  silkscreen extent -1.58,-0.87 1.58,0.87, body extent -1.55,-1.4 1.55,1.4, height 1.4
ESD_QFN2_1P6X1_P125 [mm]
  rect 0.55x0.8 smd mask+0.05: 1(-0.625,0) 2(0.625,0)
  silkscreen extent -1,-0.55 0.85,0.55, body extent -0.85,-0.55 0.85,0.55, height 0.61
ESD_QFN1610_2N_1K_2A [mm] "DFN, 2-Leads, Body 1.60x1.00mm"
  rect 0.55x0.9 smd mask+0.05: 1(-0.625,0) 2(0.625,0)
  silkscreen extent -1.02,-0.58 0.85,0.58, body extent -0.85,-0.55 0.85,0.55, height 0.6
ESD_QFN-6L_1P7X1P5_P050 [mm]
  rect 0.25x0.6 smd mask+0.05: 1(-0.5,-0.65) 2(0,-0.65) 3(0.5,-0.65) 4(0.5,0.65) 5(0,0.65) 6(-0.5,0.65)
  silkscreen extent -0.9,-0.8 0.9,0.8, body extent -0.9,-0.8 0.9,0.8, height 0.56
ESD_SOT23 [mm]
  rect 1x1.4 smd mask+0.05: 1(-0.95,-1.1) 2(0.95,-1.1) 3(0,1.1)
  silkscreen extent -1.63,-0.82 1.63,0.82, body extent -1.56,-1.5 1.56,1.5, height 1.4
ESD_SOT23-6L [mm]
  rect 0.6x1.2 smd mask+0.05: 1(-0.95,-1.15) 2(0,-1.15) 3(0.95,-1.15) 4(0.95,1.15) 5(0,1.15) 6(-0.95,1.15)
  silkscreen extent -1.53,-0.87 1.53,0.87, body extent -1.52,-1.5 1.52,1.5, height 1.45
ESD_SOT323-5L [mm]
  rect 0.4x1.2 smd mask+0.05: 1(-0.65,-0.85) 2(0,-0.85) 3(0.65,-0.85) 4(0.65,0.85) 5(-0.65,0.85)
  silkscreen extent -1.22,-1.21 1.22,0.77, body extent -1.15,-1.05 1.15,1.05, height 1.1
ESD_ST0201 [mm]
  rect 0.425x0.33 smd mask+0.05: 1(-0.312,0) 2(0.312,0)
  silkscreen extent -0.55,-0.3 0.33,0.3, body extent -0.34,-0.18 0.34,0.18, height 0.34
ICC_DFN6-EPAD_3X3_P095 [mm]
  rect 0.45x0.5 smd mask+0.05: 1(-0.95,-1.3) 2(0,-1.3) 3(0.95,-1.3) 4(0.95,1.3) 5(0,1.3) 6(-0.95,1.3)
  rect 2.5x1.7 smd mask+0.05: EP(0,0)
  silkscreen extent -1.55,-1.55 1.55,1.55, body extent -1.55,-1.55 1.55,1.55, height 1
ICC_LQFP64_10X10_P050 [mm]
  rect 0.3x1.7 smd mask+0.05: 1(-3.75,-5.9) 2(-3.25,-5.9) 3(-2.75,-5.9) 4(-2.25,-5.9) 5(-1.75,-5.9) 6(-1.25,-5.9) 7(-0.75,-5.9) 8(-0.25,-5.9) 9(0.25,-5.9) 10(0.75,-5.9) 11(1.25,-5.9) 12(1.75,-5.9) 13(2.25,-5.9) 14(2.75,-5.9) 15(3.25,-5.9) 16(3.75,-5.9) 33(3.75,5.9) 34(3.25,5.9) 35(2.75,5.9) 36(2.25,5.9) 37(1.75,5.9) 38(1.25,5.9) 39(0.75,5.9) 40(0.25,5.9) 41(-0.25,5.9) 42(-0.75,5.9) 43(-1.25,5.9) 44(-1.75,5.9) 45(-2.25,5.9) 46(-2.75,5.9) 47(-3.25,5.9) 48(-3.75,5.9)
  rect 1.7x0.3 smd mask+0.05: 17(5.9,-3.75) 18(5.9,-3.25) 19(5.9,-2.75) 20(5.9,-2.25) 21(5.9,-1.75) 22(5.9,-1.25) 23(5.9,-0.75) 24(5.9,-0.25) 25(5.9,0.25) 26(5.9,0.75) 27(5.9,1.25) 28(5.9,1.75) 29(5.9,2.25) 30(5.9,2.75) 31(5.9,3.25) 32(5.9,3.75) 49(-5.9,3.75) 50(-5.9,3.25) 51(-5.9,2.75) 52(-5.9,2.25) 53(-5.9,1.75) 54(-5.9,1.25) 55(-5.9,0.75) 56(-5.9,0.25) 57(-5.9,-0.25) 58(-5.9,-0.75) 59(-5.9,-1.25) 60(-5.9,-1.75) 61(-5.9,-2.25) 62(-5.9,-2.75) 63(-5.9,-3.25) 64(-5.9,-3.75)
  silkscreen extent -5.05,-5.05 5.05,5.05, body extent -6,-6 6,6, height 1.6
ICC_SOT23-3L_H1P12 [mm]
  rect 1x1.4 smd mask+0.05: 1(-0.95,-1.1) 2(0.95,-1.1) 3(0,1.1)
  silkscreen extent -1.63,-0.82 1.63,0.82, body extent -1.56,-1.25 1.56,1.25, height 1.12
ICC_SOT23-5L_H1P45 [mm]
  rect 0.6x1.3 smd mask+0.05: 1(-0.95,-1.1) 2(0,-1.1) 3(0.95,-1.1) 4(0.95,1.1) 5(-0.95,1.1)
  silkscreen extent -1.75,-1.68 1.6,0.97, body extent -1.52,-1.25 1.52,1.25, height 1.45
ICC_TSOP65P640X110_HS-17N [mm] "MCD-01593"
  rect 1.15x0.45 smd mask+0.05: 1(-2.775,2.275) 2(-2.775,1.625) 3(-2.775,0.975) 4(-2.775,0.325) 5(-2.775,-0.325) 6(-2.775,-0.975) 7(-2.775,-1.625) 8(-2.775,-2.275) 9(2.775,-2.275) 10(2.775,-1.625) 11(2.775,-0.975) 12(2.775,-0.325) 13(2.775,0.325) 14(2.775,0.975) 15(2.775,1.625) 16(2.775,2.275)
  rect 2.95x3.6 smd paste+0 mask+0.05: 17(0,0)
  silkscreen extent -1.98,-2.5 1.85,2.5, body extent -3.2,-2.55 3.2,2.55, height 1.1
